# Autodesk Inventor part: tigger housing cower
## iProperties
Created: 2006-04
Part Number: tigger housing cower
Document SubType Name: Modeling
Designer: Калинин
Author: Калинин
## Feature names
1. Выдавливание1 [Extrusion]
2. Выдавливание2 [Extrusion]
3. Оболочка1
4. Отверстие1 [Hole]
5. Выдавливание3 [Extrusion]
6. Выдавливание4 [Extrusion]
7. Выдавливание5 [Extrusion]
8. Выдавливание6 [Extrusion]
9. Выдавливание7 [Extrusion]
10. Фаска1 [Chamfer]
11. Выдавливание8 [Extrusion]
12. Сопряжение1 [Fillet]
13. Сопряжение2 [Fillet]
14. Сопряжение3 [Fillet]
15. Сопряжение4 [Fillet]
16. Сопряжение5 [Fillet]
17. Сопряжение6 [Fillet]
